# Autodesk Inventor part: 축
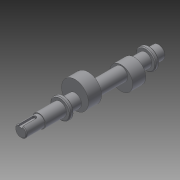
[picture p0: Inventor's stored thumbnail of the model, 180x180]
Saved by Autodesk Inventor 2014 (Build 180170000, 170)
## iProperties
Created: 2014-12
Part Number: 축
Material: 일반
Document SubType Name: Modeling
Designer: Owner
Density: 1 g/cm^3
Appearance: 기본값
Author: Owner
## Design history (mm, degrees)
sketch "스케치1"
  geometry: L1 (-90, 0)-(90, 0); L2 (-90, 0)-(-90, 7.5); L3 (-90, 7.5)-(-66, 7.5); L4 (-66, 7.5)-(-66, 8.5); L5 (-66, 8.5)-(-39, 8.5); L6 (-39, 8.5)-(-39, 13); L7 (-39, 13)-(-34, 13); L8 (-34, 13)-(-34, 8.5); L9 (-34, 8.5)-(72, 8.5); L10 (72, 8.5)-(72, 13); L11 (72, 13)-(77, 13); L12 (77, 13)-(77, 8.5); L13 (77, 8.5)-(90, 8.5); L14 (90, 8.5)-(90, 0); 4 further points
  constraints: 28 end point, 6 parallel, 5 perpendicular, 3 midpoint, 3 point on line, 2 horizontal, 1 coincident, 1 horizontal alignment
  dimensions: "d0" = 180 distance of L1.start L1.end; "d1" = 24 distance of L2.end L3.end; "d2" = 27 distance of L4.end L5.end; "d3" = 5 distance of L6.end L7.end; "d4" = 5 distance of L10.end L11.end; "d5" = 13 distance of L12.end L13.end; "d6" = 15 diameter of L3 L1; "d7" = 17 diameter of L5 L1; "d8" = 26 diameter of L7 L1
revolve "회전1" sketch "스케치1" stored, may be unused: angle "d9" = 90 deg
node "작업 평면1"
sketch "스케치2"
  geometry: 1 further point
sketch "스케치3"
  geometry: C1 r 17.5 at (0, 6); 1 further point
  constraints: 1 centre point, 1 vertical alignment
  dimensions: "d11" = 35 diameter of C1; "d12" = 6 distance of point (0, 0) C1.centre
extrude "돌출1" join sketch "스케치3" distance "d13" = 17; taper "d14" = 0 deg
node "작업 평면2"
sketch "스케치4"
  geometry: C1 r 15 at (0, -5); 1 further point
  constraints: 1 centre point, 1 vertical alignment
  dimensions: "d16" = 30 diameter of C1; "d17" = 5 distance of C1.centre point (0, 0)
extrude "돌출2" join sketch "스케치4" distance "d18" = 17; taper "d19" = 0 deg
node "작업 평면3"
sketch "스케치5"
  geometry: L1 (0, 5.5)-(0, -9.552); L2 (-2.5, 5.5)-(-2.5, -12); L3 (2.5, -12)-(2.5, 5.5); L4 (7.5, -12)-(-7.5, -12) reference; L5 (-2.5, -12)-(2.5, -12); A1 r 2.5 centre (0, 5.5) between (2.5, 5.5) and (-2.5, 5.5); 3 further points
  constraints: 10 end point, 2 midpoint, 2 point on circle, 2 point on line, 2 tangent, 1 centre point, 1 parallel, 1 perpendicular, 1 vertical, 1 vertical alignment
  dimensions: "d20" = 5 distance between parallel lines of L3 L2; "d21" = 20 dimension on A1 L4
extrude "돌출3" cut sketch "스케치5" distance "d22" = 3; taper "d23" = 0 deg
chamfer "모따기1" distance "d24" = 1; stored, may be unused: second distance "d25" = 2, angle "d26" = 45 deg
node "솔리드1"
other parameters: "d10" = -19.5, "d15" = 40.5
